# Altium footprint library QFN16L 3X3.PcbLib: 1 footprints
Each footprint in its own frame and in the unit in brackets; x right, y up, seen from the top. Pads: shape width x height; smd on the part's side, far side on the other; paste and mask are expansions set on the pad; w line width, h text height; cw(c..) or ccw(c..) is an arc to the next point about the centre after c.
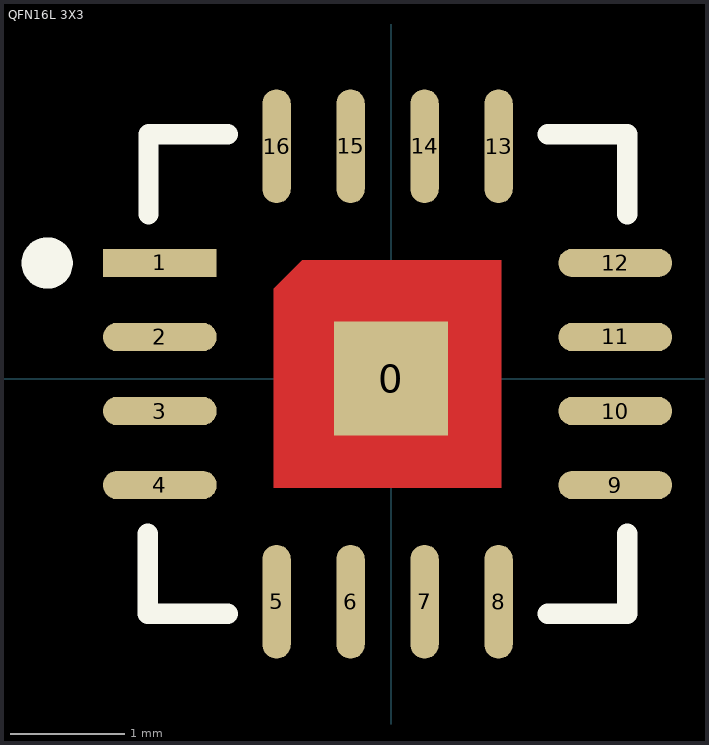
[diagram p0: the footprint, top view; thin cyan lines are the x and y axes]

## QFN16L 3X3 [mm]
pads (17):
  rect 1x1 smd: 0(0,0)
  rect 1x0.25 smd: 1(-2.032,1.016)
  oval 1x0.25 smd: 2(-2.032,0.366) 3(-2.032,-0.284) 4(-2.032,-0.934) 9(1.968,-0.934) 10(1.968,-0.284) 11(1.968,0.366) 12(1.968,1.016)
  oval 0.25x1 smd: 5(-1.007,-1.959) 6(-0.357,-1.959) 7(0.293,-1.959) 8(0.943,-1.959) 13(0.943,2.041) 14(0.293,2.041) 15(-0.357,2.041) 16(-1.007,2.041)
Top Layer:
  region: 0.968,1.041 0.968,-0.959 -1.032,-0.959 -1.032,0.791 -0.782,1.041
Top Overlay:
  circle w0.25: c-3.021,1.016 r0.1
  lines w0.178: -2.138,-1.363 -2.138,-2.065 -1.436,-2.065 ; -2.132,1.445 -2.132,2.147 -1.436,2.147 ; 1.372,-2.065 2.074,-2.065 2.074,-1.363 ; 1.372,2.147 2.074,2.147 2.074,1.445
